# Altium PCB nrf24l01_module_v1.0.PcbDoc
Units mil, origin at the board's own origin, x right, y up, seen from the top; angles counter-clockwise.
Board outline 1151.03 x 600.03 mil, 2 copper layers (Top Layer, Bottom Layer); 19 components, 17 nets, 68 pads, 62 vias.
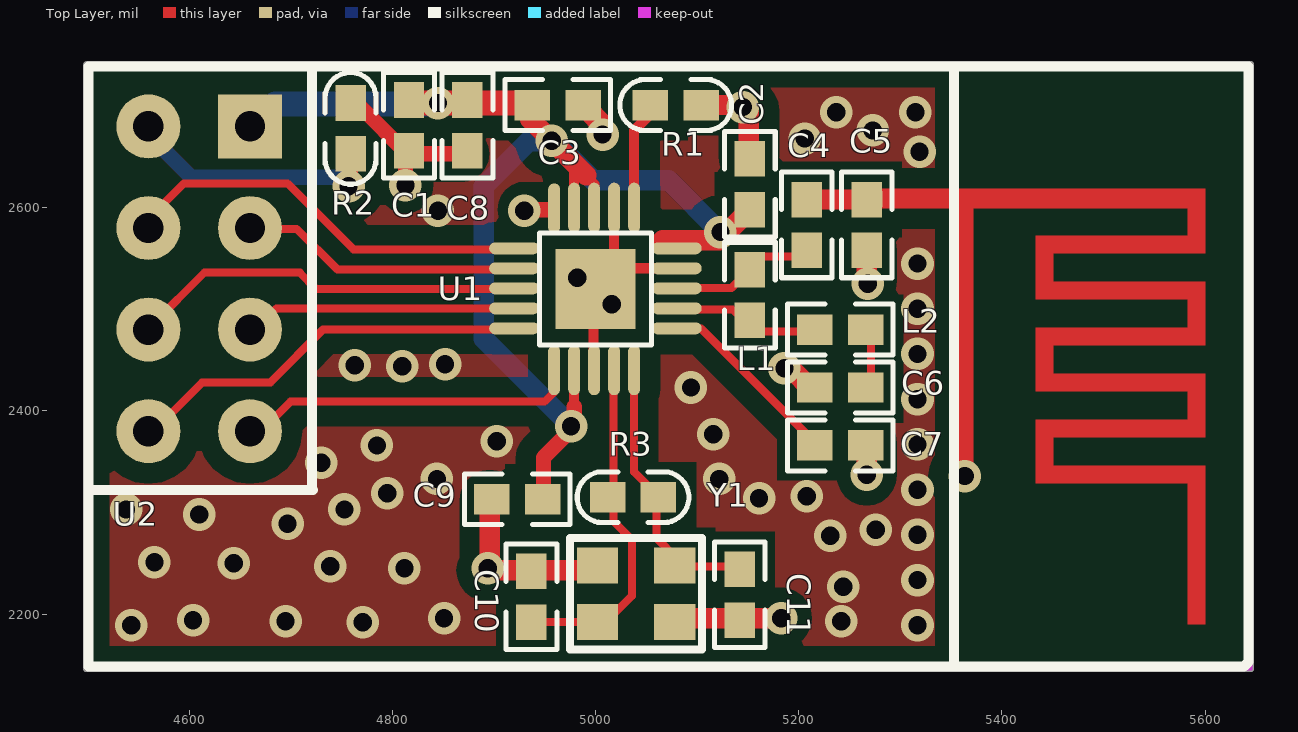
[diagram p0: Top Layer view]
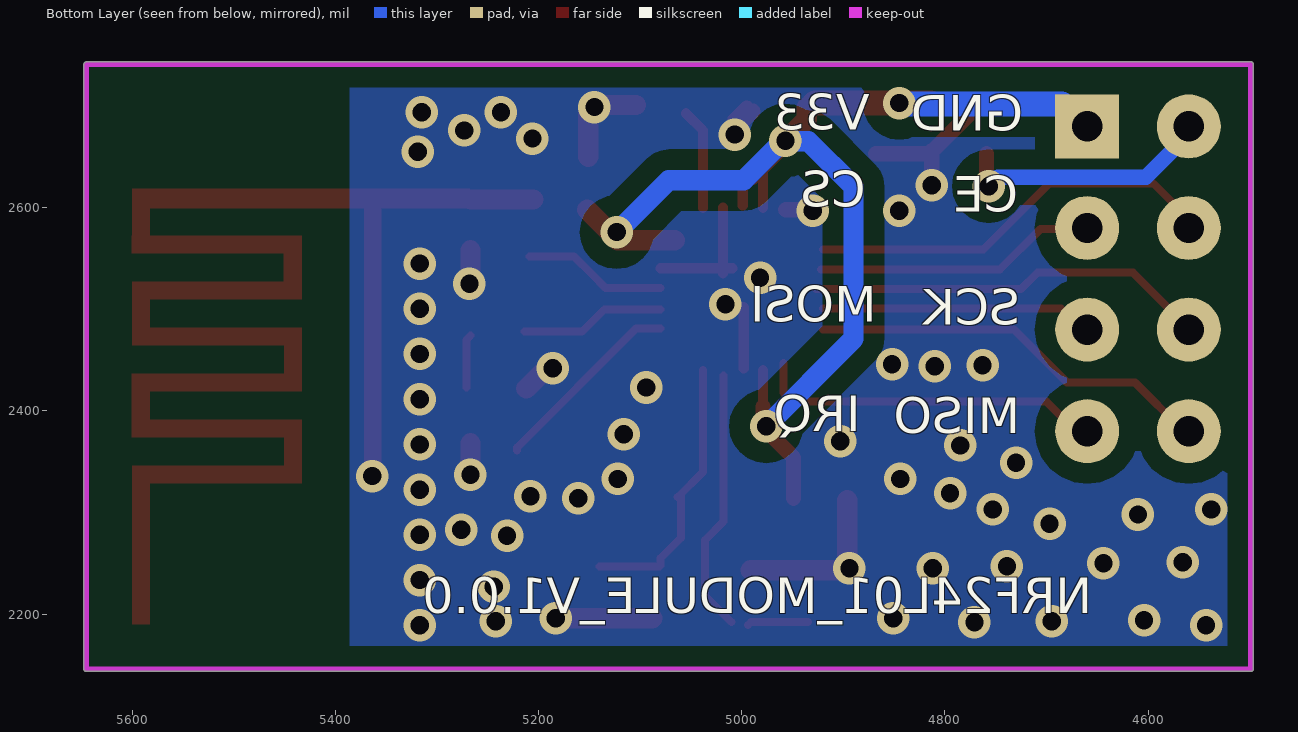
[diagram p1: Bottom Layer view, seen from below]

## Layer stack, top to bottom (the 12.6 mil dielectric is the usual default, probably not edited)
Top Layer: signal copper 1.4
Dielectric: dielectric 12.6, FR-4, Dk 4.8
Bottom Layer: signal copper 1.4

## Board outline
4496.48,2146 ccw(c4499,2146) 4499,2143.49 5645,2143.49 ccw(c5645,2146) 5647.52,2146 5647.52,2741 ccw(c5645,2741) 5645,2743.51 4499,2743.51 ccw(c4499,2741) 4496.48,2741

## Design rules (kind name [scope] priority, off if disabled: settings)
Clearance Clearance_1 [(InPolygon)] p1: gap=20
Clearance [All] p2: gap=7.87
ComponentClearance [All] p1 off: gap=10 collisioncheckmode=3 verticalgap=10
HoleSize [All] p1 off: absolutevalues=TRUE maxlimit=100 minlimit=1 maxpercent=80.000 minpercent=20.000
LayerPairs [All] p1 off: enforce=TRUE
PlaneConnect [All] p1: planeconnectstyle=Direct reliefexpansion=20 reliefentries=4 reliefconductorwidth=10 reliefairgap=10
PolygonConnect [All] p1: connectstyle=Direct reliefconductorwidth=10 reliefentries=4 polygonreliefangle="90 Angle"
RoutingVias [All] p1: holewidth=14 width=24 viastyle="Through Hole" minholewidth=12 minwidth=20 maxholewidth=28 maxwidth=50
SolderMaskExpansion [All] p1: expansion=4
TestPointUsage [All] p1: valid=0 allowmultiple=FALSE
Testpoint [All] p1: side=15 testpointundercomponent=TRUE minsize=40 maxsize=100 preferedsize=60 minholesize=0 maxholesize=40 preferedholesize=32 testpointgrid=1 style=1023 order=0123456789
Width [All] p1: maxlimit=200 minlimit=7.87 preferedwidth=10
15 further rules are at their usual default settings.

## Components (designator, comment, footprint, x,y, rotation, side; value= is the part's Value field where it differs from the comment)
C1 "4.7 uF" C0402 4816.5,2681 r180 top
C2 "0.1uF" C0402 5152,2623 r0 top
C3 "0.1uF" C0402 4963,2701 r270 top
C4 "1.5pF" C0402 5208,2583 r0 top
C5 "1pF" C0402 5267,2583 r0 top
C6 "4.7pF" C0402 5241,2423 r90 top
C7 "2.2nF" C0402 5241,2366 r270 top
C8 "0.01uF" C0402 4874,2681 r180 top
C9 "1nF" C0402 4923,2313 r90 top
C10 "22pF" C0402 4937,2217 r0 top
C11 "22pF" C0402 5142,2219 r180 top
L1 "Inductor" C0402 5152,2514 r0 top
L2 "Inductor" C0402 5241,2480 r270 top
R1 "22K" "R0402 -1" 5079,2701 r270 top
R2 "0R" "R0402 -1" 4759,2678 r0 top
R3 "1M" "R0402 -1" 5037,2315 r90 top
U1 "nRF24L01" QFN-20_4x4_NRF24L01 4920,2560 r0 top
U2 "NRF24L01" NRF24L01_MODE 4560,2680 r180 top locked
Y1 "16M" CRYSTAL_RSX-10 5040,2220 r0 top

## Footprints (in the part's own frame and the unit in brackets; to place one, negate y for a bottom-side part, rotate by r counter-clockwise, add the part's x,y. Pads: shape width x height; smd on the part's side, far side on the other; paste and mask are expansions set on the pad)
C0402 [mil] "SMT电容"
  rect 30x35 smd: 1(0,-25) 2(0,25)
  silkscreen extent -25,-52 25,52, body extent -11,-20 11,20, height 20
CRYSTAL_RSX-10 [mm]
  rect 1.03x0.9 smd: 1(-0.965,-0.705) 2(0.965,-0.705) 3(0.965,0.705) 4(-0.965,0.705)
  silkscreen extent -1.65,-1.4 1.65,1.4, body extent -1.6,-1.27 1.61,1.24, height 0.7
NRF24L01_MODE [mm]
  round 1.6 hole 0.762: 1(0,0) 3(0,2.54) 4(-2.54,2.54) 5(0,5.08) 6(-2.54,5.08) 7(0,7.62) 8(-2.54,7.62)
  rect 1.6x1.6 hole 0.762: 2(-2.54,0)
  silkscreen extent -27.5,-1.5 1.5,13.5
QFN-20_4x4_NRF24L01 [mm] "QFN, 20-Leads, Body 4.0x4.0mm (max), Pitch 0.50mm, IPC Medium Density"
  oval 1.25x0.3 smd: 1(0,0) 2(0,-0.5) 3(0,-1) 4(0,-1.5) 5(0,-2) 11(4.064,-2) 12(4.064,-1.5) 13(4.064,-1) 14(4.064,-0.5) 15(4.064,0)
  round 0.5 on Top Overlay: 3(0.254,0.635)
  oval 0.3x1.25 smd: 6(1,-3.048) 7(1.5,-3.048) 8(2,-3.048) 9(2.5,-3.048) 10(3,-3.048) 16(3,1.016) 17(2.5,1.016) 18(2,1.016) 19(1.5,1.016) 20(1,1)
  rect 2x2 smd: 21(2.032,-1.016)
  silkscreen extent 0.64,-2.41 3.43,0.38, body extent 0.53,-2.54 3.53,0.46, height 0.62
"R0402 -1" [mil] "SMT电阻"
  rect 30x35 smd: 1(0,-25) 2(0,25)
  silkscreen extent -25,-55 25,55, body extent -10,-20 10,20, height 15

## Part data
C1 C2 C3 C4 C5 C6 C7 C8 C9 C10 C11: library part CAP, "SMT电容"
R1 R2 R3: library part RES1, "SMT电阻"
U1: library part nRF24L01_CHIP, "NRF24L01"
Y1: library part XTAL, "Crystal Oscillator"

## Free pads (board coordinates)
  rect 15.75x15.75 smd: 1(5274.56,2608.67) 2(5363.54,2335.84)

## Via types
v1: diameter 32, hole 18, Top Layer to Bottom Layer, tented both sides, 62 vias

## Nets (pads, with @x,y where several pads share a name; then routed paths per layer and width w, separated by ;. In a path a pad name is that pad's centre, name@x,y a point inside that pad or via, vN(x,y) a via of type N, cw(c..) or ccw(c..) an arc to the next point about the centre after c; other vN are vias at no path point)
DC3.3V: C1.1 C2.1 C3.1 C8.1 C9.1 U1.7 U1.15 U1.18 U1.19 U2.2 | length 1257.2
  Top Layer w10: 4979.06,2404 U1.7 ; U1.19 4979.06,2643.94 ; 4992,2630 4999,2623 U1.18@4999,2602
  Top Layer w15: C9.1@4949,2314 4949,2354 4979.06,2384.06 4979.06,2404
  Top Layer w20: C3.1@4936,2699 4936,2687 4991,2632 ; 5066,2568 5122,2568 C2.1
  Top Layer w25: C1.1@4814,2703 C3.1@4928,2703
  Bottom Layer w20: v1@4958,2667 4998,2627 5072,2627 v1(5123,2576) ; v1@4959.5,2665.5 4934.5,2665.5 4890,2621 4890,2471 v1@4977,2384
  Bottom Layer w25: U2.2@4668,2685 4685,2702 v1@4839,2702
  other v1: 4976,2385 4957,2666 4845,2703
GND: C1.2 C2.2 C3.2 C5.1 C6.2 C7.2 C8.2 C9.2 C10.2 C11.2 R1.2 R2.2 U1.8 U1.14 U1.17 U1.20 U1.21 Y1.2 Y1.4 | length 881.5
  Top Layer w10: U1.8@4998,2442 U1.21@4998,2502 ; U1.21@5009.31,2540.32 U1.14 ; U1.21@5018.43,2535.43 U1.17
  Top Layer w15: R2.2@4761,2700 4768,2700 4815,2653 C8.2@4868,2653 ; v1(4813,2622) C1.2@4813,2656 ; v1@4931,2598 U1.20@4957,2598 ; C3.2@4989,2695 5006,2678 v1@5006,2670 ; C3.2@4995,2698 v1@5007,2686
  Top Layer w20: C9.2@4896,2312 4896,2246 4893,2243 Y1.4@4991,2243 ; Y1.2@5088,2196 v1(5183,2196) ; R1.2 5146,2701 5151,2696 C2.2@5151,2650 ; v1@5188,2440 5194,2440 C6.2@5212,2422 ; v1(5267,2337) C7.2@5267,2368 ; v1@5267,2528 C5.1
  other v1: 4543,2189 5317,2189 4771,2192 4695,2193 5242,2193 4604,2194 4851,2196 5244,2227 5317,2233.5 4812,2245 4894,2245 4739,2247 4644,2250 4566,2251 5231,2277 5317,2278 5276,2283 4697,2289 4610,2298 4538,2303 4753,2303 5161,2314 5208,2316 4795,2319 5317,2322.5 4844,2333 5122,2333 4730,2349 4785,2366 5317,2367 4903,2370 5116,2377 5317,2411.5 5094,2423 5186,2442 4810,2444 4763,2445 4852,2446 5317,2456 5317,2500.5 5016,2505 5268,2525 4982,2531 5317,2545 4845,2597 4930,2597 5319,2655 5206,2668 5007,2672 5273,2676 5237,2694 5315,2694 5145,2699
NetC4_1: C4.1 L1.2 U1.13 | length 141.8
  Top Layer w7.87: U1.13@5080,2521 5134,2521 5147,2534 5165,2552 C4.1@5209,2552
NetC6_1: C6.1 L2.2 | length 52.7
  Top Layer w7.87: L2.2@5267,2474 5271,2470 C6.1@5271,2423
NetC7_1: C7.1 U1.11 | length 192.5
  Top Layer w7.87: U1.11@5080,2481 5104,2481 5221,2364 C7.1@5221,2361
NetC10_1: C10.1 R3.2 U1.9 Y1.1 | length 321.5
  Top Layer w7.87: C10.1@4935,2192 4991,2192 Y1.1@4994,2189 ; Y1.1@5010,2192 5036,2218 5036,2273 5018,2291 U1.9@5018,2435
NetC11_1: C11.1 R3.1 U1.10 Y1.3 | length 271
  Top Layer w7.87: U1.10 5038.11,2339.89 R3.1@5063,2315 ; R3.1@5060,2315 5060,2275 5080,2255 5080,2248 5081,2247 C11.1@5140,2247
NetL1_1: L1.1 L2.1 U1.12 | length 143.1
  Top Layer w7.87: U1.12@5080,2500 5135,2500 5157,2478 L2.1@5214,2478
NetR1_1: R1.1 U1.16 | length 100
  Top Layer w10: U1.16 5038.11,2676.11 R1.1@5055,2693
NRF_ANT: C4.2 C5.2 pad.1 pad.2 | length 62
  Top Layer w20: C4.2@5205,2608 C5.2
NRF_CE: U1.1 U2.3 | length 407.1
  Top Layer w7.87: U2.3@4556,2585 4595,2624 4697,2624 4762,2559 U1.1@4920,2559
NRF_CS: U1.2 U2.4 | length 275.6
  Top Layer w7.87: U2.4@4663,2579 4706,2579 4746,2539 U1.2@4922,2539
NRF_IRQ: U1.6 U2.8 | length 337
  Top Layer w7.87: U2.8@4668,2377 4700,2409 4950,2409 4959,2418 U1.6@4959,2447
NRF_MISO: U1.5 U2.7 | length 393.6
  Top Layer w7.87: U2.7@4567,2382 4613,2428 4680,2428 4732,2480 U1.5@4920,2480
NRF_MOSI: U1.4 U2.6 | length 260.9
  Top Layer w7.87: U2.6@4667,2482 4686,2501 U1.4@4920,2501
NRF_SCK: U1.3@4920,2520.63 U2.5 | length 390.8
  Top Layer w7.87: U2.5@4564,2485 4615,2536 4709,2536 4725,2520 U1.3@4927,2520
RF_GND: R2.1 U2.1 | length 242.6
  Top Layer w15: v1@4759,2620 R2.1
  Bottom Layer w15: U2.1@4566,2666 4602,2630 4748,2630 v1(4757,2621)
pads on no net: U1.3@4930,2585
copper on no net:
  other v1: 5363.54,2335.84

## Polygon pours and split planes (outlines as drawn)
GND on Top Layer "Top Layer-GND" (solid): 4509.43,2741 4511.57,2739 5334,2739 5334,2148 5330.79,2151 4503,2151 4503,2731 4509.43,2737
GND on Bottom Layer "Bottom Layer-GND" (solid): 4503,2737 4504,2738 5386,2738 5386,2147 5387,2146 5385,2148 4500,2148 4500,2734 4504,2738

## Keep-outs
Keep-Out Layer:
  lines w5: 4507,2146 5645,2146 5645,2741 4499,2741 4499,2146 4520,2146

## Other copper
Top Layer:
  region net NRF_ANT: 5266.73,2618.98 5266.73,2599.32 5600.32,2599.32 5600.32,2618.98
  region net NRF_ANT: 5433,2346.2 5433,2328.47 5600.35,2328.47 5600.35,2346.2
  region net NRF_ANT: 5433,2391.4 5433,2328.47 5450.73,2328.47 5450.73,2391.4
  region net NRF_ANT: 5433,2391.4 5433,2373.67 5600.43,2373.67 5600.43,2391.4
  region net NRF_ANT: 5582.6,2436.75 5582.6,2373.67 5600.43,2373.67 5600.43,2436.75
  region net NRF_ANT: 5433,2436.75 5433,2418.97 5600.33,2418.97 5600.33,2436.75
  region net NRF_ANT: 5433,2482 5433,2418.97 5450.73,2418.97 5450.73,2482
  region net NRF_ANT: 5433,2482 5433,2464.27 5600.33,2464.27 5600.33,2482
  region net NRF_ANT: 5582.6,2527.3 5582.6,2464.27 5600.33,2464.27 5600.33,2527.3
  region net NRF_ANT: 5433.05,2527.3 5433.05,2509.59 5600.33,2509.59 5600.33,2527.3
  region net NRF_ANT: 5433.04,2572.58 5433.04,2509.57 5450.78,2509.57 5450.78,2572.58
  region net NRF_ANT: 5433.04,2572.58 5433.04,2555.01 5600.52,2555.01 5600.52,2572.58
  region net NRF_ANT: 5582.65,2618.98 5582.65,2555.01 5600.32,2555.01 5600.32,2618.98
  region net NRF_ANT: 5354.34,2608.01 5354.34,2327.3 5372.01,2327.3 5372.01,2608.01
  region net NRF_ANT: 5582.65,2346.2 5582.65,2189.69 5600.35,2189.69 5600.35,2346.2

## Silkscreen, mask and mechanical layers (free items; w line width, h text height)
Bottom Overlay:
  text "V33" at 4874,2665 h60
  text "GND" at 4723,2664 h60
  text "CS" at 4878,2589 h60
  text "CE" at 4728,2584 h60
  text "MOSI" at 4867,2476 h60
  text "SCK" at 4726,2473 h60
  text "IRQ" at 4883,2368 h60
  text "MISO" at 4726,2366 h60
  text "NRF24L01_MODULE_V1.0.0" at 4655,2189 h60
Top Solder:
  region: 5582.65,2346.2 5582.65,2189.69 5600.35,2189.69 5600.35,2346.2
  region: 5433,2346.2 5433,2328.47 5600.35,2328.47 5600.35,2346.2
  region: 5354.34,2608.01 5354.34,2327.3 5372.01,2327.3 5372.01,2608.01
  region: 5266.73,2618.98 5266.73,2599.32 5600.32,2599.32 5600.32,2618.98
  region: 5433.04,2572.58 5433.04,2555.01 5600.52,2555.01 5600.52,2572.58
  region: 5433.05,2527.3 5433.05,2509.59 5600.33,2509.59 5600.33,2527.3
  region: 5433,2482 5433,2464.27 5600.33,2464.27 5600.33,2482
  region: 5433,2482 5433,2418.97 5450.73,2418.97 5450.73,2482
  region: 5433,2391.4 5433,2373.67 5600.43,2373.67 5600.43,2391.4
  region: 5433,2436.75 5433,2418.97 5600.33,2418.97 5600.33,2436.75
  region: 5433.04,2572.58 5433.04,2509.57 5450.78,2509.57 5450.78,2572.58
  region: 5582.65,2618.98 5582.65,2555.01 5600.32,2555.01 5600.32,2618.98
  region: 5582.6,2436.75 5582.6,2373.67 5600.43,2373.67 5600.43,2436.75
  region: 5433,2391.4 5433,2328.47 5450.73,2328.47 5450.73,2391.4
  region: 5582.6,2527.3 5582.6,2464.27 5600.33,2464.27 5600.33,2527.3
